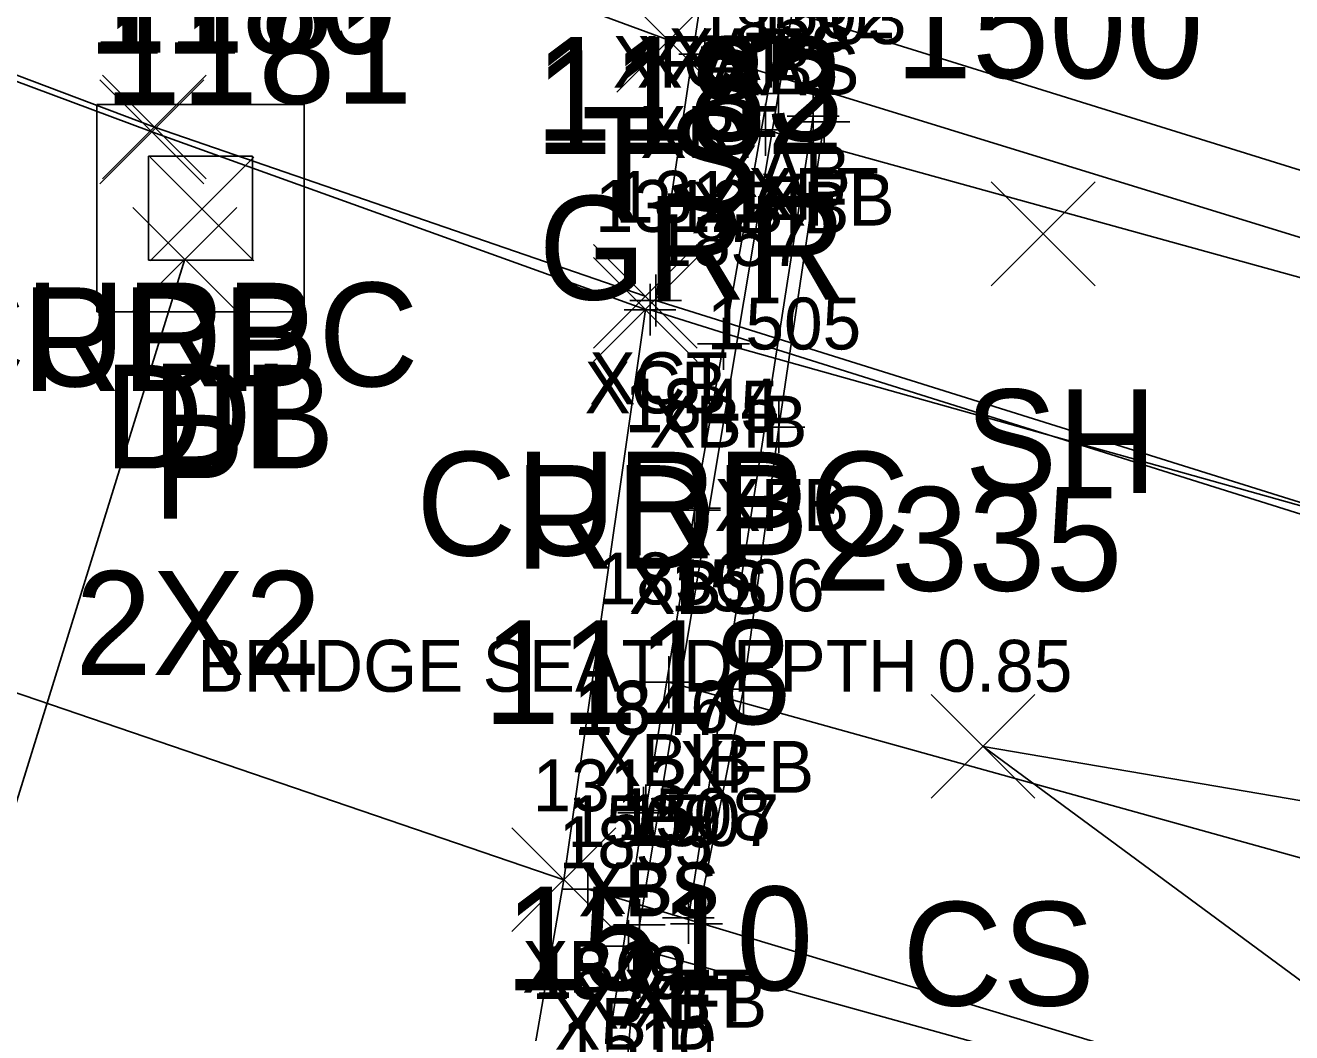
# Model space of a CAD drawing. Extents: x 1761340 to 1763889, y 696770 to 706023.
# Drawn here: x 1761590.31 to 1761614.72, y 700859.11 to 700878.53 of the extents above; entities that cross this region are included whole.
import ezdxf

# ---------------------------------------------------------------- set-up
doc = ezdxf.new("R2010")
doc.units = 0
for name, color, linetype in [('B_A', 7, 'Continuous'), ('B_C', 7, 'Continuous'), ('B_I', 7, 'Continuous'), ('B_TIC', 7, 'Continuous'), ('BB', 7, 'Continuous'), ('BDC', 7, 'Continuous'), ('BELB', 7, 'Continuous'), ('BF', 7, 'Continuous'), ('BFT', 7, 'Continuous'), ('BR', 7, 'Continuous'), ('BSE', 7, 'Continuous'), ('BSUBM', 7, 'Continuous'), ('D_A', 7, 'Continuous'), ('D_C', 7, 'Continuous'), ('D_I', 7, 'Continuous'), ('D_TIC', 7, 'Continuous'), ('DCP', 7, 'Continuous'), ('DS', 7, 'Continuous'), ('L_A', 7, 'Continuous'), ('L_I', 7, 'Continuous'), ('L_TIC', 7, 'Continuous'), ('LELB', 7, 'Continuous'), ('P_A', 7, 'Continuous'), ('P_I', 7, 'Continuous'), ('P_TIC', 7, 'Continuous'), ('PET', 7, 'Continuous'), ('PRC', 7, 'Continuous'), ('R_A', 7, 'Continuous'), ('R_I', 7, 'Continuous'), ('R_TIC', 7, 'Continuous'), ('RC', 7, 'Continuous'), ('RGR', 7, 'Continuous')]:
    doc.layers.add(name, color=color, linetype=linetype)

msp = doc.modelspace()

# ---------------------------------------------------------------- linework, layer by layer
at = {"layer": 'B_TIC'}
for p, q in [((1761603.407, 700877.977), (1761603.482, 700877.977)), ((1761604.83, 700877.221), (1761604.905, 700877.221)), ((1761605.497, 700876.784), (1761605.573, 700876.784)), ((1761604.578, 700876.52), (1761604.654, 700876.52)), ((1761605.708, 700876.673), (1761605.784, 700876.673)), ((1761602.462, 700873.228), (1761602.538, 700873.228)), ((1761602.353, 700873.051), (1761602.429, 700873.051)), ((1761603.769, 700872.392), (1761603.845, 700872.392)), ((1761604.835, 700870.784), (1761604.911, 700870.784)), ((1761603.21, 700869.184), (1761603.285, 700869.184)), ((1761603.211, 700869.221), (1761603.287, 700869.221)), ((1761602.719, 700865.868), (1761602.794, 700865.868)), ((1761604.158, 700865.736), (1761604.233, 700865.736)), ((1761602.231, 700863.351), (1761602.306, 700863.351)), ((1761602.272, 700863.396), (1761602.348, 700863.396)), ((1761601.152, 700861.879), (1761601.228, 700861.879)), ((1761602.148, 700861.187), (1761602.224, 700861.187)), ((1761603.093, 700861.322), (1761603.168, 700861.322)), ((1761603.251, 700861.207), (1761603.326, 700861.207)), ((1761601.939, 700860.779), (1761602.014, 700860.779))]:
    msp.add_line(p, q, dxfattribs=at)
for points in [[(1761603.404, 700877.477), (1761603.404, 700878.477)], [(1761602.904, 700877.977), (1761603.904, 700877.977)], [(1761604.826, 700876.721), (1761604.826, 700877.721)], [(1761605.494, 700876.284), (1761605.494, 700877.284)], [(1761604.326, 700877.221), (1761605.326, 700877.221)], [(1761604.575, 700876.02), (1761604.575, 700877.02)], [(1761605.705, 700876.173), (1761605.705, 700877.173)], [(1761604.994, 700876.784), (1761605.994, 700876.784)], [(1761604.075, 700876.52), (1761605.075, 700876.52)], [(1761605.205, 700876.673), (1761606.205, 700876.673)], [(1761602.459, 700872.728), (1761602.459, 700873.728)], [(1761602.35, 700872.551), (1761602.35, 700873.551)], [(1761601.959, 700873.228), (1761602.959, 700873.228)], [(1761601.85, 700873.051), (1761602.85, 700873.051)], [(1761603.766, 700871.892), (1761603.766, 700872.892)], [(1761603.266, 700872.392), (1761604.266, 700872.392)], [(1761604.832, 700870.284), (1761604.832, 700871.284)], [(1761604.332, 700870.784), (1761605.332, 700870.784)], [(1761603.206, 700868.684), (1761603.206, 700869.684)], [(1761603.208, 700868.721), (1761603.208, 700869.721)], [(1761602.706, 700869.184), (1761603.706, 700869.184)], [(1761602.708, 700869.221), (1761603.708, 700869.221)], [(1761602.715, 700865.368), (1761602.715, 700866.368)], [(1761604.154, 700865.236), (1761604.154, 700866.236)], [(1761602.215, 700865.868), (1761603.215, 700865.868)], [(1761603.654, 700865.736), (1761604.654, 700865.736)], [(1761602.227, 700862.851), (1761602.227, 700863.851)], [(1761602.269, 700862.896), (1761602.269, 700863.896)], [(1761601.727, 700863.351), (1761602.727, 700863.351)], [(1761601.769, 700863.396), (1761602.769, 700863.396)], [(1761601.149, 700861.379), (1761601.149, 700862.379)], [(1761600.649, 700861.879), (1761601.649, 700861.879)], [(1761602.145, 700860.687), (1761602.145, 700861.687)], [(1761603.089, 700860.822), (1761603.089, 700861.822)], [(1761603.247, 700860.707), (1761603.247, 700861.707)], [(1761601.645, 700861.187), (1761602.645, 700861.187)], [(1761601.935, 700860.279), (1761601.935, 700861.279)], [(1761602.589, 700861.322), (1761603.589, 700861.322)], [(1761602.747, 700861.207), (1761603.747, 700861.207)], [(1761601.435, 700860.779), (1761602.435, 700860.779)]]:
    msp.add_lwpolyline(points, dxfattribs=at)
at = {"layer": 'BB'}
for points in [[(1761604.575, 700876.52), (1761642.956, 700865.912)], [(1761603.766, 700872.392), (1761642.528, 700861.516)], [(1761602.715, 700865.868), (1761641.132, 700855.179)], [(1761601.935, 700860.779), (1761640.161, 700850.159)]]:
    msp.add_lwpolyline(points, dxfattribs=at)
at = {"layer": 'BDC'}
for points in [[(1761603.372, 700879.329), (1761602.459, 700873.228), (1761625.807, 700865.915), (1761643.998, 700861.743), (1761666.42, 700857.506), (1761686.349, 700855.322), (1761703.242, 700853.873), (1761720.711, 700853.034), (1761728.973, 700853.355), (1761729.967, 700859.215)], [(1761602.35, 700873.051), (1761625.784, 700865.689), (1761644.021, 700861.397), (1761666.64, 700857.269), (1761686.143, 700854.84), (1761703.209, 700853.454), (1761720.802, 700852.829), (1761729.026, 700852.764)]]:
    msp.add_lwpolyline(points, dxfattribs=at)
at = {"layer": 'BELB'}
msp.add_lwpolyline([(1761601.149, 700861.879), (1761622.312, 700855.499), (1761642.198, 700851.032), (1761664.959, 700846.932), (1761684.404, 700844.626), (1761702.463, 700842.89), (1761719.736, 700841.994), (1761727.361, 700840.892)], dxfattribs=at)
at = {"layer": 'BF'}
msp.add_lwpolyline([(1761603.372, 700879.329), (1761627.262, 700871.889), (1761644.624, 700867.82), (1761667.288, 700863.505), (1761686.862, 700861.108), (1761704.425, 700859.764), (1761721.12, 700859.13), (1761729.967, 700859.215)], dxfattribs=at)
at = {"layer": 'BFT'}
for points in [[(1761605.494, 700876.784), (1761603.089, 700861.322)], [(1761605.705, 700876.673), (1761604.832, 700870.784), (1761604.154, 700865.736), (1761603.247, 700861.207)]]:
    msp.add_lwpolyline(points, dxfattribs=at)
at = {"layer": 'BR'}
msp.add_lwpolyline([(1761603.404, 700877.977), (1761626.827, 700870.765), (1761644.368, 700866.459), (1761666.987, 700862.382), (1761686.603, 700859.803), (1761703.665, 700858.606), (1761720.831, 700858.025), (1761729.539, 700857.943)], dxfattribs=at)
at = {"layer": 'BSE'}
msp.add_lwpolyline([(1761604.97, 700879.202), (1761603.208, 700869.221), (1761603.206, 700869.184), (1761602.269, 700863.396), (1761602.227, 700863.351), (1761601.457, 700858.276), (1761601.422, 700858.259), (1761600.545, 700852.441), (1761600.535, 700852.421), (1761599.823, 700846.766)], dxfattribs=at)
at = {"layer": 'BSUBM'}
msp.add_lwpolyline([(1761604.855, 700882.521), (1761605.668, 700882.23), (1761604.826, 700877.221), (1761602.145, 700861.187), (1761601.761, 700856.927), (1761600.323, 700849.766)], dxfattribs=at)
at = {"layer": 'D_TIC'}
for points in [[(1761592.714, 700873.99), (1761594.714, 700875.99)], [(1761594.714, 700873.99), (1761592.714, 700875.99)], [(1761592.381, 700873.024), (1761594.381, 700875.024)], [(1761594.381, 700873.024), (1761592.381, 700875.024)]]:
    msp.add_lwpolyline(points, dxfattribs=at)
at = {"layer": 'DCP'}
msp.add_lwpolyline([(1761581.514, 700835.771), (1761593.381, 700874.024)], dxfattribs=at)
at = {"layer": 'DS'}
for p, q in [((1761591.683, 700877.008), (1761595.683, 700877.008)), ((1761591.683, 700873.008), (1761591.683, 700877.008)), ((1761595.683, 700877.008), (1761595.683, 700873.008)), ((1761592.683, 700874.008), (1761592.683, 700876.008)), ((1761592.683, 700876.008), (1761594.683, 700876.008)), ((1761594.683, 700876.008), (1761594.683, 700874.008)), ((1761593.688, 700875.009), (1761593.688, 700875.009)), ((1761593.688, 700875.009), (1761593.688, 700875.009)), ((1761594.683, 700874.008), (1761592.683, 700874.008)), ((1761595.683, 700873.008), (1761591.683, 700873.008))]:
    msp.add_line(p, q, dxfattribs=at)
at = {"layer": 'L_TIC'}
for points in [[(1761608.93, 700873.514), (1761610.93, 700875.514)], [(1761610.93, 700873.514), (1761608.93, 700875.514)], [(1761607.772, 700863.631), (1761609.772, 700865.631)], [(1761609.772, 700863.631), (1761607.772, 700865.631)]]:
    msp.add_lwpolyline(points, dxfattribs=at)
at = {"layer": 'LELB'}
msp.add_lwpolyline([(1761639.915, 700830.601), (1761631.782, 700838.831), (1761628.56, 700843.668), (1761624.344, 700853.144), (1761608.772, 700864.631), (1761621.099, 700862.527), (1761628.557, 700864.432)], dxfattribs=at)
at = {"layer": 'P_TIC'}
for points in [[(1761591.745, 700875.48), (1761593.745, 700877.48)], [(1761593.745, 700875.48), (1761591.745, 700877.48)], [(1761601.26, 700872.054), (1761603.26, 700874.054)], [(1761603.26, 700872.054), (1761601.26, 700874.054)], [(1761599.688, 700861.06), (1761601.688, 700863.06)], [(1761601.688, 700861.06), (1761599.688, 700863.06)], [(1761599.688, 700861.06), (1761601.688, 700863.06)], [(1761601.688, 700861.06), (1761599.688, 700863.06)]]:
    msp.add_lwpolyline(points, dxfattribs=at)
at = {"layer": 'PET'}
msp.add_lwpolyline([(1761551.015, 700866.825), (1761575.841, 700857.112), (1761588.612, 700852.655), (1761598.439, 700849.106), (1761600.688, 700862.06), (1761602.26, 700873.054), (1761592.745, 700876.48), (1761583.21, 700880.042), (1761565.694, 700887.32), (1761551.927, 700894.01)], dxfattribs=at)
at = {"layer": 'PRC'}
msp.add_lwpolyline([(1761371.661, 701058.145), (1761390.633, 701031.264), (1761404.648, 701011.453), (1761424.14, 700985.995), (1761443.925, 700962.202), (1761463.212, 700942.493), (1761486.68, 700921.951), (1761508.059, 700906.418), (1761533.506, 700890.818), (1761557.035, 700878.891), (1761580.259, 700869.028), (1761600.688, 700862.06)], dxfattribs=at)
at = {"layer": 'R_TIC'}
for points in [[(1761601.711, 700877.245), (1761603.711, 700879.245)], [(1761603.711, 700877.245), (1761601.711, 700879.245)], [(1761591.794, 700875.572), (1761593.794, 700877.572)], [(1761593.794, 700875.572), (1761591.794, 700877.572)], [(1761601.258, 700872.311), (1761603.258, 700874.311)], [(1761603.258, 700872.311), (1761601.258, 700874.311)]]:
    msp.add_lwpolyline(points, dxfattribs=at)
at = {"layer": 'RC'}
msp.add_lwpolyline([(1761602.258, 700873.311), (1761592.794, 700876.572), (1761583.275, 700880.167), (1761565.849, 700887.443)], dxfattribs=at)
at = {"layer": 'RGR'}
msp.add_lwpolyline([(1761602.711, 700878.245), (1761585.074, 700884.738), (1761568.333, 700892.416), (1761556.016, 700899.061)], dxfattribs=at)

# ---------------------------------------------------------------- texts
at = {"layer": 'B_A'}
for s, p in [('XAT', (1761602.701, 700877.477)), ('XFAT', (1761601.628, 700877.329)), ('XCT', (1761602.092, 700877.329)), ('XBS', (1761603.71, 700877.202)), ('XAT', (1761603.587, 700877.181)), ('XRF', (1761602.163, 700875.977)), ('XAB', (1761603.547, 700875.221)), ('XFT', (1761604.238, 700874.784)), ('XBIB', (1761603.146, 700874.52)), ('XFB', (1761604.465, 700874.673)), ('XCT', (1761601.179, 700871.228)), ('XCB', (1761601.086, 700871.051)), ('XBIB', (1761602.337, 700870.392)), ('XFB', (1761603.592, 700868.784)), ('XBS', (1761601.947, 700867.184)), ('XBS', (1761601.948, 700867.221)), ('XBIB', (1761601.286, 700863.868)), ('XFB', (1761602.914, 700863.736)), ('XBS', (1761600.968, 700861.351)), ('XBS', (1761601.009, 700861.396)), ('XBC', (1761599.885, 700859.879)), ('XAB', (1761600.865, 700859.187)), ('XFT', (1761601.833, 700859.322)), ('XFB', (1761602.007, 700859.207)), ('XBIB', (1761600.506, 700858.779))]:
    msp.add_text(s, height=1, dxfattribs=at).set_placement(p)
at = {"layer": 'B_C'}
msp.add_text('BRIDGE SEAT DEPTH 0.85', height=1, dxfattribs=at).set_placement((1761593.624, 700865.684))
at = {"layer": 'B_I'}
for s, p in [('1502', (1761604.108, 700878.284)), ('1503', (1761604.319, 700878.173)), ('1858', (1761603.229, 700878.02)), ('1312', (1761601.287, 700874.551)), ('1311', (1761601.679, 700874.728)), ('1857', (1761602.419, 700873.892)), ('1505', (1761603.446, 700872.284)), ('1845', (1761601.86, 700870.684)), ('1844', (1761601.861, 700870.721)), ('1856', (1761601.341, 700867.368)), ('1506', (1761602.741, 700867.236)), ('1847', (1761600.881, 700864.851)), ('1846', (1761600.895, 700864.896)), ('1313', (1761600.086, 700863.379)), ('1508', (1761601.703, 700862.822)), ('1509', (1761600.755, 700862.687)), ('1507', (1761601.862, 700862.707)), ('1855', (1761600.589, 700862.279)), ('1849', (1761600.072, 700859.759)), ('1848', (1761600.11, 700859.776)), ('1510', (1761600.655, 700858.427))]:
    msp.add_text(s, height=1, dxfattribs=at).set_placement(p)
at = {"layer": 'D_A'}
for s, p in [('DIB', (1761591.816, 700869.99)), ('DI', (1761592.743, 700870.009)), ('P', (1761592.759, 700869.024))]:
    msp.add_text(s, height=2, dxfattribs=at).set_placement(p)
at = {"layer": 'D_C'}
msp.add_text('2X2', height=2, dxfattribs=at).set_placement((1761591.263, 700866.009))
at = {"layer": 'D_I'}
for s, p in [('1180', (1761591.501, 700877.99)), ('1179', (1761591.555, 700878.009)), ('1181', (1761591.822, 700877.024))]:
    msp.add_text(s, height=2, dxfattribs=at).set_placement(p)
at = {"layer": 'L_A'}
for s, p in [('TS', (1761601.028, 700874.961)), ('SH', (1761608.418, 700869.514)), ('CS', (1761607.213, 700859.631))]:
    msp.add_text(s, height=2, dxfattribs=at).set_placement(p)
at = {"layer": 'L_I'}
for s, p in [('1500', (1761607.072, 700877.514)), ('2335', (1761605.512, 700867.631)), ('1510', (1761599.549, 700859.927))]:
    msp.add_text(s, height=2, dxfattribs=at).set_placement(p)
at = {"layer": 'P_A'}
for p in [(1761590.234, 700871.48), (1761599.748, 700868.054)]:
    msp.add_text('RDP', height=2, dxfattribs=at).set_placement(p)
at = {"layer": 'P_I'}
for s, p in [('1182', (1761600.134, 700876.054)), ('1118', (1761599.13, 700865.06)), ('1118', (1761599.13, 700865.06))]:
    msp.add_text(s, height=2, dxfattribs=at).set_placement(p)
at = {"layer": 'R_A'}
for s, p in [('GRR', (1761600.2, 700873.245)), ('CURBC', (1761588.376, 700871.572)), ('CURBC', (1761597.841, 700868.311))]:
    msp.add_text(s, height=2, dxfattribs=at).set_placement(p)
at = {"layer": 'R_I'}
msp.add_text('1183', height=2, dxfattribs=at).set_placement((1761600.132, 700876.311))

doc.saveas('drawing.dxf')
